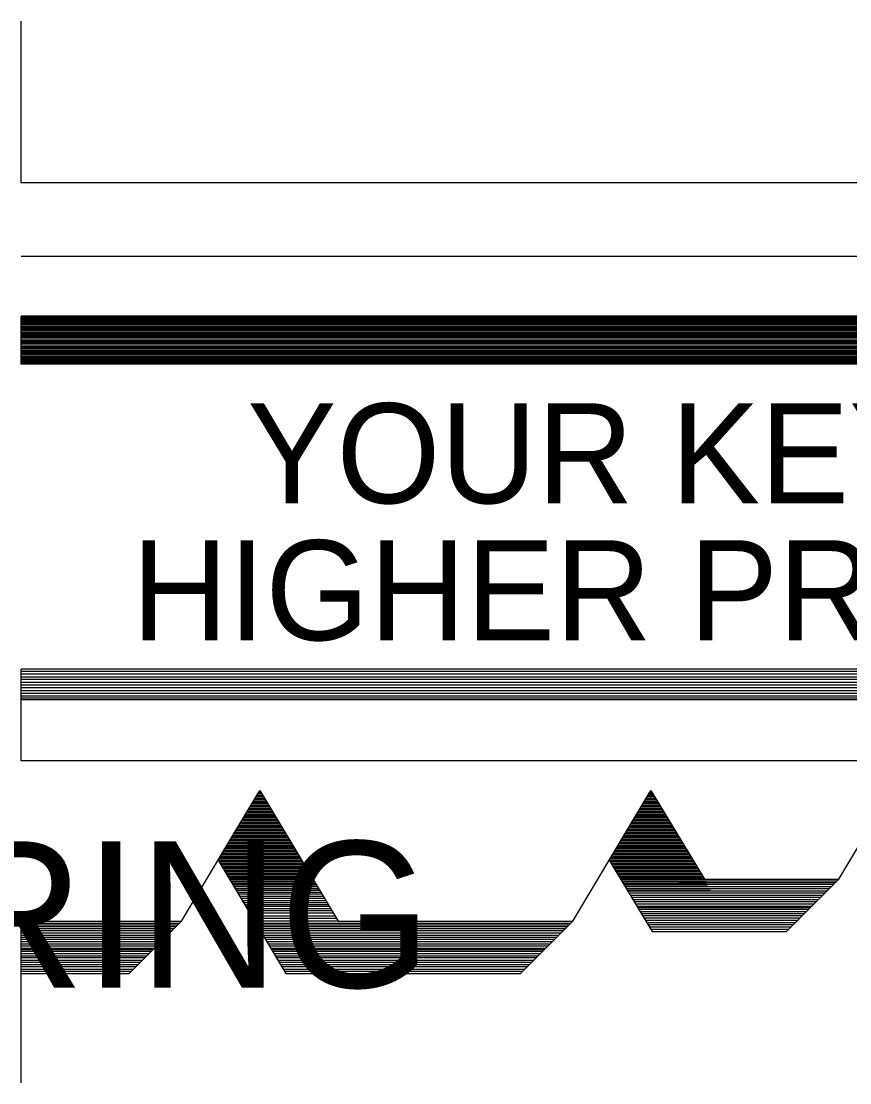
# Model space of a CAD drawing. Extents: x 22369.6 to 22428.3, y 22369.6 to 22415.
# Drawn here: x 22373.576 to 22374.324, y 22371.131 to 22372.089 of the extents above; entities that cross this region are included whole.
import ezdxf

# ---------------------------------------------------------------- set-up
doc = ezdxf.new("R2010")
doc.units = 0
for name, color, linetype in [('Level 1', 7, 'Continuous'), ('Level 10', 7, 'Continuous'), ('Level 2', 7, 'Continuous'), ('Level 7', 7, 'Continuous')]:
    doc.layers.add(name, color=color, linetype=linetype)

msp = doc.modelspace()

# ---------------------------------------------------------------- linework, layer by layer
at = {"layer": 'Level 1'}
msp.add_line((22373.57652, 22371.77921), (22373.57652, 22371.82271), dxfattribs=at)
at = {"layer": 'Level 10'}
msp.add_line((22375.01852, 22371.87637), (22373.57652, 22371.87637), dxfattribs=at)
at = {"layer": 'Level 2'}
for p, q in [((22375.08335, 22371.82271), (22373.57652, 22371.82271)), ((22375.08469, 22371.82171), (22373.57652, 22371.82171)), ((22375.08585, 22371.82071), (22373.57652, 22371.82071)), ((22375.08719, 22371.81954), (22373.57652, 22371.81954)), ((22375.08869, 22371.81837), (22373.57652, 22371.81837)), ((22375.09002, 22371.81721), (22373.57652, 22371.81721)), ((22375.09169, 22371.81587), (22373.57652, 22371.81587)), ((22375.09302, 22371.81471), (22373.57652, 22371.81471)), ((22375.09469, 22371.81337), (22373.57652, 22371.81337)), ((22375.09635, 22371.81204), (22373.57652, 22371.81204)), ((22375.09769, 22371.81087), (22373.57652, 22371.81087)), ((22375.09919, 22371.80954), (22373.57652, 22371.80954)), ((22375.10102, 22371.80821), (22373.57652, 22371.80821)), ((22375.10235, 22371.80704), (22373.57652, 22371.80704)), ((22375.10369, 22371.80587), (22373.57652, 22371.80587)), ((22375.10535, 22371.80454), (22373.57652, 22371.80454)), ((22375.10702, 22371.80321), (22373.57652, 22371.80321)), ((22375.10852, 22371.80187), (22373.57652, 22371.80187)), ((22375.11035, 22371.80037), (22373.57652, 22371.80037)), ((22375.11185, 22371.79921), (22373.57652, 22371.79921)), ((22375.11335, 22371.79787), (22373.57652, 22371.79787)), ((22375.11519, 22371.79637), (22373.57652, 22371.79637)), ((22375.11685, 22371.79504), (22373.57652, 22371.79504)), ((22375.11802, 22371.79404), (22373.57652, 22371.79404)), ((22375.11969, 22371.79271), (22373.57652, 22371.79271)), ((22375.12119, 22371.79137), (22373.57652, 22371.79137)), ((22375.12269, 22371.79021), (22373.57652, 22371.79021)), ((22375.12402, 22371.78904), (22373.57652, 22371.78904)), ((22375.12535, 22371.78804), (22373.57652, 22371.78804)), ((22375.12719, 22371.78654), (22373.57652, 22371.78654)), ((22375.12835, 22371.78554), (22373.57652, 22371.78554)), ((22375.12969, 22371.78437), (22373.57652, 22371.78437)), ((22375.13085, 22371.78337), (22373.57652, 22371.78337)), ((22375.13219, 22371.78237), (22373.57652, 22371.78237)), ((22375.13319, 22371.78154), (22373.57652, 22371.78154)), ((22375.13435, 22371.78054), (22373.57652, 22371.78054)), ((22375.13519, 22371.77987), (22373.57652, 22371.77987)), ((22375.13602, 22371.77921), (22373.57652, 22371.77921)), ((22375.21319, 22371.50387), (22373.57652, 22371.50387)), ((22373.57652, 22371.42121), (22373.57652, 22371.50387)), ((22375.21052, 22371.50171), (22373.57652, 22371.50171)), ((22375.20769, 22371.49937), (22373.57652, 22371.49937)), ((22375.20452, 22371.49671), (22373.57652, 22371.49671)), ((22375.20185, 22371.49454), (22373.57652, 22371.49454)), ((22375.19869, 22371.49187), (22373.57652, 22371.49187)), ((22375.19585, 22371.48954), (22373.57652, 22371.48954)), ((22375.19285, 22371.48704), (22373.57652, 22371.48704)), ((22375.18952, 22371.48437), (22373.57652, 22371.48437)), ((22375.18652, 22371.48187), (22373.57652, 22371.48187)), ((22375.18369, 22371.47954), (22373.57652, 22371.47954)), ((22375.18169, 22371.47787), (22373.57652, 22371.47787)), ((22375.17985, 22371.47637), (22373.57652, 22371.47637)), ((22375.11319, 22371.42121), (22373.57652, 22371.42121)), ((22373.79002, 22371.39154), (22373.79369, 22371.39154)), ((22373.79085, 22371.39287), (22373.79285, 22371.39287)), ((22374.14285, 22371.39121), (22374.14685, 22371.39121)), ((22374.14352, 22371.39221), (22374.14619, 22371.39221)), ((22374.14402, 22371.39321), (22374.14569, 22371.39321)), ((22373.78452, 22371.38221), (22373.79919, 22371.38221)), ((22373.78519, 22371.38354), (22373.79835, 22371.38354)), ((22373.78602, 22371.38487), (22373.79769, 22371.38487)), ((22373.78685, 22371.38621), (22373.79685, 22371.38621)), ((22373.78769, 22371.38754), (22373.79602, 22371.38754)), ((22373.78852, 22371.38887), (22373.79519, 22371.38887)), ((22373.78919, 22371.39021), (22373.79452, 22371.39021)), ((22374.13752, 22371.38221), (22374.15219, 22371.38221)), ((22374.13819, 22371.38354), (22374.15135, 22371.38354)), ((22374.13902, 22371.38487), (22374.15069, 22371.38487)), ((22374.13985, 22371.38621), (22374.14985, 22371.38621)), ((22374.14069, 22371.38754), (22374.14902, 22371.38754)), ((22374.14152, 22371.38887), (22374.14819, 22371.38887)), ((22374.14219, 22371.39021), (22374.14752, 22371.39021)), ((22373.77902, 22371.37287), (22373.80485, 22371.37287)), ((22373.77985, 22371.37421), (22373.80402, 22371.37421)), ((22373.78069, 22371.37554), (22373.80319, 22371.37554)), ((22373.78119, 22371.37687), (22373.80235, 22371.37687)), ((22373.78202, 22371.37821), (22373.80169, 22371.37821)), ((22373.78285, 22371.37954), (22373.80085, 22371.37954)), ((22373.78369, 22371.38087), (22373.80002, 22371.38087)), ((22374.13202, 22371.37287), (22374.15785, 22371.37287)), ((22374.13285, 22371.37421), (22374.15702, 22371.37421)), ((22374.13369, 22371.37554), (22374.15619, 22371.37554)), ((22374.13419, 22371.37687), (22374.15535, 22371.37687)), ((22374.13502, 22371.37821), (22374.15469, 22371.37821)), ((22374.13585, 22371.37954), (22374.15385, 22371.37954)), ((22374.13669, 22371.38087), (22374.15302, 22371.38087)), ((22373.77252, 22371.36221), (22373.81119, 22371.36221)), ((22373.77335, 22371.36354), (22373.81035, 22371.36354)), ((22373.77402, 22371.36487), (22373.80952, 22371.36487)), ((22373.77485, 22371.36621), (22373.80885, 22371.36621)), ((22373.77569, 22371.36754), (22373.80802, 22371.36754)), ((22373.77652, 22371.36887), (22373.80719, 22371.36887)), ((22373.77735, 22371.37021), (22373.80635, 22371.37021)), ((22373.77819, 22371.37154), (22373.80569, 22371.37154)), ((22374.12552, 22371.36221), (22374.16419, 22371.36221)), ((22374.12635, 22371.36354), (22374.16335, 22371.36354)), ((22374.12702, 22371.36487), (22374.16252, 22371.36487)), ((22374.12785, 22371.36621), (22374.16185, 22371.36621)), ((22374.12869, 22371.36754), (22374.16102, 22371.36754)), ((22374.12952, 22371.36887), (22374.16019, 22371.36887)), ((22374.13035, 22371.37021), (22374.15935, 22371.37021)), ((22374.13119, 22371.37154), (22374.15869, 22371.37154)), ((22373.76719, 22371.35287), (22373.81685, 22371.35287)), ((22373.76769, 22371.35421), (22373.81602, 22371.35421)), ((22373.76852, 22371.35554), (22373.81519, 22371.35554)), ((22373.76935, 22371.35687), (22373.81435, 22371.35687)), ((22373.77002, 22371.35821), (22373.81352, 22371.35821)), ((22373.77085, 22371.35954), (22373.81285, 22371.35954)), ((22373.77169, 22371.36087), (22373.81202, 22371.36087)), ((22374.12019, 22371.35287), (22374.16985, 22371.35287)), ((22374.12069, 22371.35421), (22374.16902, 22371.35421)), ((22374.12152, 22371.35554), (22374.16819, 22371.35554)), ((22374.12235, 22371.35687), (22374.16735, 22371.35687)), ((22374.12302, 22371.35821), (22374.16652, 22371.35821)), ((22374.12385, 22371.35954), (22374.16585, 22371.35954)), ((22374.12469, 22371.36087), (22374.16502, 22371.36087)), ((22373.76135, 22371.34354), (22373.82235, 22371.34354)), ((22373.76219, 22371.34487), (22373.82152, 22371.34487)), ((22373.76302, 22371.34621), (22373.82069, 22371.34621)), ((22373.76385, 22371.34754), (22373.82002, 22371.34754)), ((22373.76469, 22371.34887), (22373.81919, 22371.34887)), ((22373.76552, 22371.35021), (22373.81835, 22371.35021)), ((22373.76635, 22371.35154), (22373.81752, 22371.35154)), ((22374.11435, 22371.34354), (22374.17535, 22371.34354)), ((22374.11519, 22371.34487), (22374.17452, 22371.34487)), ((22374.11602, 22371.34621), (22374.17369, 22371.34621)), ((22374.11685, 22371.34754), (22374.17302, 22371.34754)), ((22374.11769, 22371.34887), (22374.17219, 22371.34887)), ((22374.11852, 22371.35021), (22374.17135, 22371.35021)), ((22374.11935, 22371.35154), (22374.17052, 22371.35154)), ((22373.75569, 22371.33421), (22373.82785, 22371.33421)), ((22373.75652, 22371.33554), (22373.82719, 22371.33554)), ((22373.75735, 22371.33687), (22373.82635, 22371.33687)), ((22373.75802, 22371.33821), (22373.82552, 22371.33821)), ((22373.75885, 22371.33954), (22373.82469, 22371.33954)), ((22373.75969, 22371.34087), (22373.82402, 22371.34087)), ((22373.76052, 22371.34221), (22373.82319, 22371.34221)), ((22374.10869, 22371.33421), (22374.18085, 22371.33421)), ((22374.10952, 22371.33554), (22374.18019, 22371.33554)), ((22374.11035, 22371.33687), (22374.17935, 22371.33687)), ((22374.11102, 22371.33821), (22374.17852, 22371.33821)), ((22374.11185, 22371.33954), (22374.17769, 22371.33954)), ((22374.11269, 22371.34087), (22374.17702, 22371.34087)), ((22374.11352, 22371.34221), (22374.17619, 22371.34221)), ((22373.75419, 22371.33154), (22373.81535, 22371.22921)), ((22373.75419, 22371.33154), (22373.82952, 22371.33154)), ((22373.75485, 22371.33287), (22373.82869, 22371.33287)), ((22373.75502, 22371.33021), (22373.83035, 22371.33021)), ((22373.75585, 22371.32887), (22373.83119, 22371.32887)), ((22373.75652, 22371.32754), (22373.83185, 22371.32754)), ((22373.75735, 22371.32621), (22373.83269, 22371.32621)), ((22373.75819, 22371.32487), (22373.83319, 22371.32487)), ((22374.10719, 22371.33154), (22374.14585, 22371.26721)), ((22374.10719, 22371.33154), (22374.18252, 22371.33154)), ((22374.10785, 22371.33287), (22374.18169, 22371.33287)), ((22374.10802, 22371.33021), (22374.18335, 22371.33021)), ((22374.10885, 22371.32887), (22374.18419, 22371.32887)), ((22374.10952, 22371.32754), (22374.18485, 22371.32754)), ((22374.11035, 22371.32621), (22374.18569, 22371.32621)), ((22374.11119, 22371.32487), (22374.18619, 22371.32487)), ((22373.75902, 22371.32354), (22373.83402, 22371.32354)), ((22373.75969, 22371.32221), (22373.83485, 22371.32221)), ((22373.76052, 22371.32087), (22373.83569, 22371.32087)), ((22373.76135, 22371.31954), (22373.83652, 22371.31954)), ((22373.76219, 22371.31821), (22373.83735, 22371.31821)), ((22373.76302, 22371.31687), (22373.83819, 22371.31687)), ((22373.76369, 22371.31554), (22373.83902, 22371.31554)), ((22373.76452, 22371.31421), (22373.83985, 22371.31421)), ((22374.11202, 22371.32354), (22374.18702, 22371.32354)), ((22374.11269, 22371.32221), (22374.18785, 22371.32221)), ((22374.11352, 22371.32087), (22374.18869, 22371.32087)), ((22374.11435, 22371.31954), (22374.18952, 22371.31954)), ((22374.11519, 22371.31821), (22374.19035, 22371.31821)), ((22374.11602, 22371.31687), (22374.19119, 22371.31687)), ((22374.11669, 22371.31554), (22374.19202, 22371.31554)), ((22374.11752, 22371.31421), (22374.19285, 22371.31421)), ((22374.26719, 22371.26721), (22374.31435, 22371.31437)), ((22373.76535, 22371.31287), (22373.84069, 22371.31287)), ((22373.76602, 22371.31187), (22373.84135, 22371.31187)), ((22373.76669, 22371.31054), (22373.84202, 22371.31054)), ((22373.76752, 22371.30921), (22373.84285, 22371.30921)), ((22373.76835, 22371.30771), (22373.84385, 22371.30771)), ((22373.76935, 22371.30604), (22373.84485, 22371.30604)), ((22374.11835, 22371.31287), (22374.19369, 22371.31287)), ((22374.11902, 22371.31187), (22374.19435, 22371.31187)), ((22374.11969, 22371.31054), (22374.19502, 22371.31054)), ((22374.12052, 22371.30921), (22374.19585, 22371.30921)), ((22374.12135, 22371.30771), (22374.19685, 22371.30771)), ((22374.12235, 22371.30604), (22374.19785, 22371.30604)), ((22374.16985, 22371.31271), (22374.31269, 22371.31271)), ((22374.16985, 22371.31121), (22374.31119, 22371.31121)), ((22374.16985, 22371.30971), (22374.30969, 22371.30971)), ((22374.16985, 22371.30787), (22374.30785, 22371.30787)), ((22374.16985, 22371.30604), (22374.30602, 22371.30604)), ((22373.77035, 22371.30454), (22373.84569, 22371.30454)), ((22373.77135, 22371.30271), (22373.84685, 22371.30271)), ((22373.77235, 22371.30104), (22373.84769, 22371.30104)), ((22373.77369, 22371.29904), (22373.84902, 22371.29904)), ((22373.77469, 22371.29721), (22373.85002, 22371.29721)), ((22373.77585, 22371.29521), (22373.85119, 22371.29521)), ((22374.12335, 22371.30454), (22374.19869, 22371.30454)), ((22374.12385, 22371.30387), (22374.30385, 22371.30387)), ((22374.12502, 22371.30187), (22374.30185, 22371.30187)), ((22374.12619, 22371.29987), (22374.29985, 22371.29987)), ((22374.12735, 22371.29804), (22374.29802, 22371.29804)), ((22374.12852, 22371.29604), (22374.29602, 22371.29604)), ((22373.77702, 22371.29321), (22373.85252, 22371.29321)), ((22373.77802, 22371.29154), (22373.85352, 22371.29154)), ((22373.77902, 22371.28987), (22373.85452, 22371.28987)), ((22373.78035, 22371.28787), (22373.85569, 22371.28787)), ((22373.78135, 22371.28604), (22373.85669, 22371.28604)), ((22374.12969, 22371.29404), (22374.29402, 22371.29404)), ((22374.13085, 22371.29204), (22374.29202, 22371.29204)), ((22374.13219, 22371.29004), (22374.29002, 22371.29004)), ((22374.13285, 22371.28871), (22374.28869, 22371.28871)), ((22374.13385, 22371.28721), (22374.28719, 22371.28721)), ((22373.67385, 22371.22921), (22373.72102, 22371.27637)), ((22373.78252, 22371.28404), (22373.85785, 22371.28404)), ((22373.78419, 22371.28137), (22373.85952, 22371.28137)), ((22373.78552, 22371.27921), (22373.86085, 22371.27921)), ((22373.78685, 22371.27687), (22373.86219, 22371.27687)), ((22374.02702, 22371.22921), (22374.07419, 22371.27637)), ((22374.13502, 22371.28521), (22374.28519, 22371.28521)), ((22374.13619, 22371.28321), (22374.28319, 22371.28321)), ((22374.13719, 22371.28154), (22374.28152, 22371.28154)), ((22374.13852, 22371.27937), (22374.27935, 22371.27937)), ((22374.13969, 22371.27737), (22374.27735, 22371.27737)), ((22373.57652, 22371.27471), (22373.71935, 22371.27471)), ((22373.57652, 22371.27321), (22373.71785, 22371.27321)), ((22373.57652, 22371.27171), (22373.71635, 22371.27171)), ((22373.57652, 22371.26987), (22373.71452, 22371.26987)), ((22373.57652, 22371.26804), (22373.71269, 22371.26804)), ((22373.78819, 22371.27471), (22374.07252, 22371.27471)), ((22373.78902, 22371.27321), (22374.07102, 22371.27321)), ((22373.79002, 22371.27171), (22374.06952, 22371.27171)), ((22373.79102, 22371.26987), (22374.06769, 22371.26987)), ((22373.79219, 22371.26804), (22374.06585, 22371.26804)), ((22374.14102, 22371.27537), (22374.27535, 22371.27537)), ((22374.14202, 22371.27354), (22374.27352, 22371.27354)), ((22374.14352, 22371.27121), (22374.27119, 22371.27121)), ((22374.14469, 22371.26921), (22374.26919, 22371.26921)), ((22374.14585, 22371.26721), (22374.26719, 22371.26721)), ((22373.57652, 22371.26587), (22373.71052, 22371.26587)), ((22373.57652, 22371.26387), (22373.70852, 22371.26387)), ((22373.57652, 22371.26187), (22373.70652, 22371.26187)), ((22373.57652, 22371.26004), (22373.70469, 22371.26004)), ((22373.57652, 22371.25804), (22373.70269, 22371.25804)), ((22373.79352, 22371.26587), (22374.06369, 22371.26587)), ((22373.79469, 22371.26387), (22374.06169, 22371.26387)), ((22373.79585, 22371.26187), (22374.05969, 22371.26187)), ((22373.79685, 22371.26004), (22374.05785, 22371.26004)), ((22373.79819, 22371.25804), (22374.05585, 22371.25804)), ((22373.57652, 22371.25604), (22373.70069, 22371.25604)), ((22373.57652, 22371.25404), (22373.69869, 22371.25404)), ((22373.57652, 22371.25204), (22373.69669, 22371.25204)), ((22373.57652, 22371.25071), (22373.69535, 22371.25071)), ((22373.57652, 22371.24921), (22373.69385, 22371.24921)), ((22373.57652, 22371.24721), (22373.69185, 22371.24721)), ((22373.79935, 22371.25604), (22374.05385, 22371.25604)), ((22373.80052, 22371.25404), (22374.05185, 22371.25404)), ((22373.80169, 22371.25204), (22374.04985, 22371.25204)), ((22373.80252, 22371.25071), (22374.04852, 22371.25071)), ((22373.80335, 22371.24921), (22374.04702, 22371.24921)), ((22373.80452, 22371.24721), (22374.04502, 22371.24721)), ((22373.57652, 22371.24521), (22373.68985, 22371.24521)), ((22373.57652, 22371.24354), (22373.68819, 22371.24354)), ((22373.57652, 22371.24137), (22373.68602, 22371.24137)), ((22373.57652, 22371.23937), (22373.68402, 22371.23937)), ((22373.80585, 22371.24521), (22374.04302, 22371.24521)), ((22373.80685, 22371.24354), (22374.04135, 22371.24354)), ((22373.80802, 22371.24137), (22374.03919, 22371.24137)), ((22373.80935, 22371.23937), (22374.03719, 22371.23937)), ((22373.57652, 22371.23737), (22373.68202, 22371.23737)), ((22373.57652, 22371.23554), (22373.68019, 22371.23554)), ((22373.57652, 22371.23321), (22373.67785, 22371.23321)), ((22373.57652, 22371.23121), (22373.67585, 22371.23121)), ((22373.57652, 22371.22921), (22373.67385, 22371.22921)), ((22373.81052, 22371.23737), (22374.03519, 22371.23737)), ((22373.81152, 22371.23554), (22374.03335, 22371.23554)), ((22373.81302, 22371.23321), (22374.03102, 22371.23321)), ((22373.81419, 22371.23121), (22374.02902, 22371.23121)), ((22373.81535, 22371.22921), (22374.02702, 22371.22921))]:
    msp.add_line(p, q, dxfattribs=at)
at = {"layer": 'Level 7'}
for p, q in [((22373.57652, 22371.94304), (22373.57652, 22372.08887)), ((22374.93785, 22371.94304), (22373.57652, 22371.94304)), ((22373.72102, 22371.27637), (22373.79185, 22371.39454)), ((22373.79185, 22371.39454), (22373.86252, 22371.27637)), ((22374.07419, 22371.27637), (22374.14485, 22371.39454)), ((22374.14485, 22371.39454), (22374.19302, 22371.31437)), ((22374.31435, 22371.31437), (22374.36235, 22371.39454)), ((22374.19302, 22371.31437), (22374.31435, 22371.31437)), ((22373.57652, 22371.13054), (22373.57652, 22371.27637)), ((22373.57652, 22371.27637), (22373.72102, 22371.27637)), ((22373.86252, 22371.27637), (22374.07419, 22371.27637))]:
    msp.add_line(p, q, dxfattribs=at)

# ---------------------------------------------------------------- texts
at = {"layer": 'Level 2'}
for s, height, p in [('YOUR KEY TO', 0.090249, (22373.78052, 22371.65371)), ('HIGHER PROFITS', 0.090249, (22373.67619, 22371.53004)), ('ENGINEERING', 0.13199, (22372.71135, 22371.21654))]:
    msp.add_text(s, height=height, dxfattribs=at).set_placement(p)

doc.saveas('drawing.dxf')
